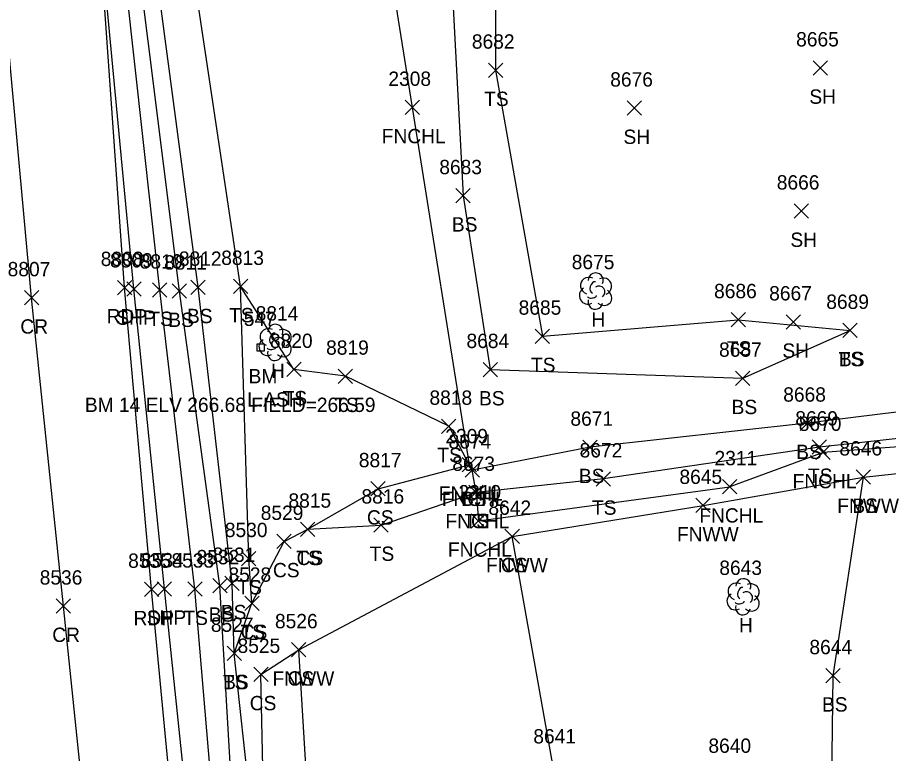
# Model space of a CAD drawing. Extents: x 1439173 to 1457902, y 641926 to 659889.
# Drawn here: x 1448353.5 to 1448474.9, y 645719.4 to 645822.1 of the extents above; entities that cross this region are included whole.
import ezdxf

# ---------------------------------------------------------------- set-up
doc = ezdxf.new("R2010")
doc.units = 0
for name, color, linetype in [('C_A', 7, 'Continuous'), ('C_C', 7, 'Continuous'), ('C_I', 7, 'Continuous'), ('CPBM', 7, 'Continuous'), ('L_A', 7, 'Continuous'), ('L_C', 7, 'Continuous'), ('L_I', 7, 'Continuous'), ('L_TIC', 7, 'Continuous'), ('LELB', 7, 'Continuous'), ('LFNC', 7, 'Continuous'), ('LTD', 7, 'Continuous'), ('P_A', 7, 'Continuous'), ('P_I', 7, 'Continuous'), ('P_TIC', 7, 'Continuous'), ('PET', 7, 'Continuous'), ('PRC', 7, 'Continuous'), ('PSP', 7, 'Continuous')]:
    doc.layers.add(name, color=color, linetype=linetype)

msp = doc.modelspace()

# ---------------------------------------------------------------- linework, layer by layer
at = {"layer": 'CPBM'}
for p, q in [((1448386.88, 645775.58), (1448386.88, 645776.58)), ((1448386.88, 645776.58), (1448387.88, 645776.58)), ((1448387.88, 645775.58), (1448386.88, 645775.58)), ((1448387.38, 645776.08), (1448387.38, 645776.08)), ((1448387.38, 645776.08), (1448387.38, 645776.08)), ((1448387.88, 645776.58), (1448387.88, 645775.58))]:
    msp.add_line(p, q, dxfattribs=at)
at = {"layer": 'L_TIC'}
for points in [[(1448419.13, 645813.76), (1448421.13, 645815.76)], [(1448421.13, 645813.76), (1448419.13, 645815.76)], [(1448464.39, 645814.07), (1448466.39, 645816.07)], [(1448466.39, 645814.07), (1448464.39, 645816.07)], [(1448407.52, 645808.57), (1448409.52, 645810.57)], [(1448409.52, 645808.57), (1448407.52, 645810.57)], [(1448438.47, 645808.47), (1448440.47, 645810.47)], [(1448440.47, 645808.47), (1448438.47, 645810.47)], [(1448414.59, 645796.25), (1448416.59, 645798.25)], [(1448416.59, 645796.25), (1448414.59, 645798.25)], [(1448461.74, 645794.11), (1448463.74, 645796.11)], [(1448463.74, 645794.11), (1448461.74, 645796.11)], [(1448377.66, 645783.47), (1448379.66, 645785.47)], [(1448379.66, 645783.47), (1448377.66, 645785.47)], [(1448383.57, 645783.59), (1448385.57, 645785.59)], [(1448385.57, 645783.59), (1448383.57, 645785.59)], [(1448372.3, 645783.08), (1448374.3, 645785.08)], [(1448374.3, 645783.08), (1448372.3, 645785.08)], [(1448375.05, 645782.94), (1448377.05, 645784.94)], [(1448377.05, 645782.94), (1448375.05, 645784.94)], [(1448452.96, 645778.95), (1448454.96, 645780.95)], [(1448454.96, 645778.95), (1448452.96, 645780.95)], [(1448460.62, 645778.64), (1448462.62, 645780.64)], [(1448462.62, 645778.64), (1448460.62, 645780.64)], [(1448468.55, 645777.46), (1448470.55, 645779.46)], [(1448470.55, 645777.46), (1448468.55, 645779.46)], [(1448468.55, 645777.46), (1448470.55, 645779.46)], [(1448470.55, 645777.46), (1448468.55, 645779.46)], [(1448425.65, 645776.65), (1448427.65, 645778.65)], [(1448427.65, 645776.65), (1448425.65, 645778.65)], [(1448391.02, 645772.01), (1448393.02, 645774.01)], [(1448393.02, 645772.01), (1448391.02, 645774.01)], [(1448418.38, 645772), (1448420.38, 645774)], [(1448420.38, 645772), (1448418.38, 645774)], [(1448398.2, 645771.07), (1448400.2, 645773.07)], [(1448400.2, 645771.07), (1448398.2, 645773.07)], [(1448453.59, 645770.78), (1448455.59, 645772.78)], [(1448455.59, 645770.78), (1448453.59, 645772.78)], [(1448412.6, 645764.08), (1448414.6, 645766.08)], [(1448414.6, 645764.08), (1448412.6, 645766.08)], [(1448462.59, 645764.52), (1448464.59, 645766.52)], [(1448464.59, 645764.52), (1448462.59, 645766.52)], [(1448432.3, 645761.16), (1448434.3, 645763.16)], [(1448434.3, 645761.16), (1448432.3, 645763.16)], [(1448464.27, 645761.19), (1448466.27, 645763.19)], [(1448466.27, 645761.19), (1448464.27, 645763.19)], [(1448464.78, 645760.44), (1448466.78, 645762.44)], [(1448466.78, 645760.44), (1448464.78, 645762.44)], [(1448415.46, 645758.71), (1448417.46, 645760.71)], [(1448417.46, 645758.71), (1448415.46, 645760.71)], [(1448415.88, 645757.97), (1448417.88, 645759.97)], [(1448417.88, 645757.97), (1448415.88, 645759.97)], [(1448415.88, 645757.97), (1448417.88, 645759.97)], [(1448417.88, 645757.97), (1448415.88, 645759.97)], [(1448434.15, 645756.74), (1448436.15, 645758.74)], [(1448436.15, 645756.74), (1448434.15, 645758.74)], [(1448470.42, 645757.01), (1448472.42, 645759.01)], [(1448472.42, 645757.01), (1448470.42, 645759.01)], [(1448470.42, 645757.01), (1448472.42, 645759.01)], [(1448472.42, 645757.01), (1448470.42, 645759.01)], [(1448402.75, 645755.37), (1448404.75, 645757.37)], [(1448404.75, 645755.37), (1448402.75, 645757.37)], [(1448451.78, 645755.65), (1448453.78, 645757.65)], [(1448453.78, 645755.65), (1448451.78, 645757.65)], [(1448416.4, 645754.87), (1448418.4, 645756.87)], [(1448418.4, 645754.87), (1448416.4, 645756.87)], [(1448416.4, 645754.87), (1448418.4, 645756.87)], [(1448418.4, 645754.87), (1448416.4, 645756.87)], [(1448448.06, 645753.04), (1448450.06, 645755.04)], [(1448450.06, 645753.04), (1448448.06, 645755.04)], [(1448416.73, 645750.89), (1448418.73, 645752.89)], [(1448418.73, 645750.89), (1448416.73, 645752.89)], [(1448392.94, 645749.73), (1448394.94, 645751.73)], [(1448394.94, 645749.73), (1448392.94, 645751.73)], [(1448392.94, 645749.73), (1448394.94, 645751.73)], [(1448394.94, 645749.73), (1448392.94, 645751.73)], [(1448403.17, 645750.31), (1448405.17, 645752.31)], [(1448405.17, 645750.31), (1448403.17, 645752.31)], [(1448421.44, 645748.73), (1448423.44, 645750.73)], [(1448423.44, 645748.73), (1448421.44, 645750.73)], [(1448421.44, 645748.73), (1448423.44, 645750.73)], [(1448423.44, 645748.73), (1448421.44, 645750.73)], [(1448389.64, 645748.02), (1448391.64, 645750.02)], [(1448391.64, 645748.02), (1448389.64, 645750.02)], [(1448384.72, 645745.63), (1448386.72, 645747.63)], [(1448386.72, 645745.63), (1448384.72, 645747.63)], [(1448382.38, 645742.17), (1448384.38, 645744.17)], [(1448384.38, 645742.17), (1448382.38, 645744.17)], [(1448377.2, 645741.37), (1448379.2, 645743.37)], [(1448379.2, 645741.37), (1448377.2, 645743.37)], [(1448380.69, 645741.83), (1448382.69, 645743.83)], [(1448382.69, 645741.83), (1448380.69, 645743.83)], [(1448385.15, 645739.4), (1448387.15, 645741.4)], [(1448387.15, 645739.4), (1448385.15, 645741.4)], [(1448385.15, 645739.4), (1448387.15, 645741.4)], [(1448387.15, 645739.4), (1448385.15, 645741.4)], [(1448382.69, 645732.41), (1448384.69, 645734.41)], [(1448384.69, 645732.41), (1448382.69, 645734.41)], [(1448382.69, 645732.41), (1448384.69, 645734.41)], [(1448384.69, 645732.41), (1448382.69, 645734.41)], [(1448391.68, 645732.91), (1448393.68, 645734.91)], [(1448393.68, 645732.91), (1448391.68, 645734.91)], [(1448391.68, 645732.91), (1448393.68, 645734.91)], [(1448393.68, 645732.91), (1448391.68, 645734.91)], [(1448386.41, 645729.47), (1448388.41, 645731.47)], [(1448388.41, 645729.47), (1448386.41, 645731.47)], [(1448466.19, 645729.29), (1448468.19, 645731.29)], [(1448468.19, 645729.29), (1448466.19, 645731.29)]]:
    msp.add_lwpolyline(points, dxfattribs=at)
at = {"layer": 'LELB'}
for points in [[(1448405.75, 645492.25), (1448401.29, 645509.86), (1448397.55, 645536.24), (1448395.04, 645565.43), (1448390.82, 645605.16), (1448386.96, 645640.23), (1448382.46, 645691.87), (1448378.2, 645742.37), (1448373.3, 645784.08), (1448367.48, 645837.06), (1448362.7, 645887.98), (1448357.78, 645935.33)], [(1448412.77, 645435.45), (1448410.01, 645448.83), (1448407.82, 645469.28), (1448405.75, 645492.25), (1448403.36, 645510.08), (1448399.67, 645536.29), (1448396.72, 645565.18), (1448393.06, 645605.09), (1448389.62, 645640.48), (1448384.68, 645691.72), (1448381.69, 645742.83), (1448376.05, 645783.94), (1448369.5, 645836.29), (1448364.45, 645888.25), (1448360.02, 645935.41)], [(1448403.36, 645510.08), (1448401.75, 645536.42), (1448399.06, 645565.21), (1448394.76, 645605.53), (1448391.92, 645640.7), (1448388.23, 645691.54), (1448383.69, 645733.41), (1448383.38, 645743.17), (1448378.66, 645784.47), (1448371.77, 645836.33), (1448366.28, 645888.78), (1448363.29, 645935.65)], [(1448383.69, 645733.41), (1448386.15, 645740.4), (1448385.72, 645746.63), (1448384.57, 645784.59), (1448376.84, 645836.17), (1448370.62, 645889.09), (1448366.48, 645935.68)], [(1448488.86, 645774.87), (1448485.16, 645804.97), (1448493.44, 645849.5), (1448484.69, 645866.76), (1448464.76, 645858.02), (1448427.96, 645849.9), (1448412.89, 645848.11), (1448415.59, 645797.25), (1448419.38, 645773), (1448454.59, 645771.78), (1448469.55, 645778.46)], [(1448493.44, 645849.5), (1448466.57, 645845.61), (1448437.38, 645832.99), (1448420.15, 645839.74), (1448420.13, 645814.76), (1448426.65, 645777.65), (1448453.96, 645779.95), (1448469.55, 645778.46)], [(1448392.02, 645773.01), (1448384.57, 645784.59)], [(1448413.6, 645765.08), (1448399.2, 645772.07), (1448392.02, 645773.01)], [(1448504.57, 645770.47), (1448489.22, 645768.67), (1448463.59, 645765.52), (1448433.3, 645762.16), (1448416.88, 645758.97)], [(1448505.1, 645766.43), (1448490.19, 645764.92), (1448465.27, 645762.19), (1448435.15, 645757.74), (1448417.4, 645755.87)], [(1448413.6, 645765.08), (1448416.46, 645759.71)], [(1448403.75, 645756.37), (1448416.46, 645759.71)], [(1448406.65, 645553.07), (1448413.88, 645573.37), (1448416.45, 645609.69), (1448416.69, 645643.68), (1448431.28, 645649.5), (1448456.82, 645674.35), (1448466.81, 645700.96), (1448467.19, 645730.29), (1448471.42, 645758.01)], [(1448386.15, 645740.4), (1448390.64, 645749.02), (1448393.94, 645750.73), (1448403.75, 645756.37)], [(1448404.17, 645751.31), (1448417.4, 645755.87)], [(1448393.94, 645750.73), (1448404.17, 645751.31)], [(1448440.92, 645562.38), (1448423.89, 645580.18), (1448428.08, 645611.99), (1448428.96, 645640.99), (1448431.28, 645649.5), (1448422.01, 645666.17), (1448428.13, 645717.84), (1448422.44, 645749.73)], [(1448388.23, 645691.54), (1448387.41, 645730.47), (1448392.68, 645733.91)]]:
    msp.add_lwpolyline(points, dxfattribs=at)
at = {"layer": 'LFNC'}
for points in [[(1448460.82, 645892.13), (1448433.93, 645874.65), (1448401.5, 645853.61), (1448408.52, 645809.57), (1448416.46, 645759.71)], [(1448504.76, 645764.38), (1448465.78, 645761.44)], [(1448408.71, 645537.14), (1448406.65, 645553.07), (1448406.84, 645570.83), (1448403.03, 645603.97), (1448399.71, 645645.27), (1448398.94, 645666), (1448395.14, 645693.25), (1448392.68, 645733.91), (1448422.44, 645749.73), (1448449.06, 645754.04), (1448471.42, 645758.01), (1448503.03, 645761.43), (1448501.38, 645735.65), (1448498.9, 645710.49)], [(1448465.78, 645761.44), (1448452.78, 645756.65)], [(1448416.88, 645758.97), (1448416.46, 645759.71)], [(1448417.4, 645755.87), (1448416.88, 645758.97)], [(1448417.73, 645751.89), (1448452.78, 645756.65)], [(1448417.4, 645755.87), (1448417.73, 645751.89)]]:
    msp.add_lwpolyline(points, dxfattribs=at)
at = {"layer": 'LTD'}
for p, q in [((1448434.05, 645784), (1448434.05, 645784)), ((1448434.05, 645784), (1448434.05, 645784)), ((1448389.37, 645776.83), (1448389.37, 645776.83)), ((1448389.37, 645776.83), (1448389.37, 645776.83)), ((1448454.62, 645741.35), (1448454.62, 645741.35)), ((1448454.62, 645741.35), (1448454.62, 645741.35))]:
    msp.add_line(p, q, dxfattribs=at)
for centre in [(1448434.09, 645785.43), (1448389.42, 645778.27), (1448454.67, 645742.78)]:
    msp.add_arc(centre, 1.05, 335.5272, 180.9563, dxfattribs=at)
for centre, major_axis, ratio, start_param, end_param in [((1448433.25, 645784.66), (1.21, -0.51), 0.895232, 1.570796, 4.712389), ((1448433.84, 645784.45), (-0.208, -0.792), 0.645439, 3.141593, 6.283185), ((1448435.09, 645784.58), (-1.14, -0.48), 0.949671, 1.570796, 4.712389), ((1448432.96, 645783.29), (0.58, -1.04), 0.959034, 3.141593, 6.283185), ((1448434.55, 645783.83), (-0.5, 0.667), 0.989748, 3.141593, 6.283185), ((1448435.05, 645783.16), (-1.09, 0.79), 0.841452, 1.570796, 4.712389), ((1448433.59, 645783.25), (-0.625, -0.083), 0.423636, 0, 3.141593), ((1448434.05, 645782.5), (0.26, 1.06), 0.942809, 1.570796, 4.712389), ((1448388.58, 645777.5), (1.21, -0.51), 0.895232, 1.570796, 4.712389), ((1448389.17, 645777.29), (-0.208, -0.792), 0.645439, 3.141593, 6.283185), ((1448390.42, 645777.41), (-1.14, -0.48), 0.949671, 1.570796, 4.712389), ((1448388.29, 645776.12), (0.58, -1.04), 0.959034, 3.141593, 6.283185), ((1448389.87, 645776.66), (-0.5, 0.667), 0.989748, 3.141593, 6.283185), ((1448390.37, 645776), (-1.09, 0.79), 0.841452, 1.570796, 4.712389), ((1448389.37, 645775.33), (0.26, 1.06), 0.942809, 1.570796, 4.712389), ((1448388.92, 645776.08), (-0.625, -0.083), 0.423636, 0, 3.141593), ((1448453.83, 645742.02), (1.21, -0.51), 0.895232, 1.570796, 4.712389), ((1448455.66, 645741.93), (-1.14, -0.48), 0.949671, 1.570796, 4.712389), ((1448453.54, 645740.64), (0.58, -1.04), 0.959034, 3.141593, 6.283185), ((1448454.41, 645741.81), (-0.208, -0.792), 0.645439, 3.141593, 6.283185), ((1448455.12, 645741.18), (-0.5, 0.667), 0.989748, 3.141593, 6.283185), ((1448454.16, 645740.6), (-0.625, -0.083), 0.423636, 0, 3.141593), ((1448455.62, 645740.52), (-1.09, 0.79), 0.841452, 1.570796, 4.712389), ((1448454.62, 645739.85), (0.26, 1.06), 0.942809, 1.570796, 4.712389)]:
    msp.add_ellipse(centre, major_axis=major_axis, ratio=ratio, start_param=start_param, end_param=end_param, dxfattribs=at)
at = {"layer": 'P_TIC'}
for points in [[(1448367.41, 645783.44), (1448369.41, 645785.44)], [(1448369.41, 645783.44), (1448367.41, 645785.44)], [(1448368.71, 645783.24), (1448370.71, 645785.24)], [(1448370.71, 645783.24), (1448368.71, 645785.24)], [(1448354.44, 645782.01), (1448356.44, 645784.01)], [(1448356.44, 645782.01), (1448354.44, 645784.01)], [(1448371.16, 645741.34), (1448373.16, 645743.34)], [(1448373.16, 645741.34), (1448371.16, 645743.34)], [(1448372.95, 645741.41), (1448374.95, 645743.41)], [(1448374.95, 645741.41), (1448372.95, 645743.41)], [(1448358.88, 645739), (1448360.88, 645741)], [(1448360.88, 645739), (1448358.88, 645741)]]:
    msp.add_lwpolyline(points, dxfattribs=at)
at = {"layer": 'PET'}
msp.add_lwpolyline([(1448443.5, 645192.53), (1448434.94, 645239.98), (1448429.99, 645267.41), (1448423.88, 645303.9), (1448416.59, 645352.86), (1448409.48, 645406.38), (1448407.14, 645423.82), (1448401.2, 645468.9), (1448395.52, 645519.79), (1448390.56, 645564.93), (1448385.73, 645605.17), (1448382.23, 645639.77), (1448376.98, 645691.5), (1448372.16, 645742.34), (1448368.41, 645784.44), (1448364.57, 645838.37), (1448359.79, 645887.7), (1448355.35, 645935.31)], dxfattribs=at)
at = {"layer": 'PRC'}
msp.add_lwpolyline([(1448432.04, 645191.01), (1448423.23, 645238.86), (1448418.18, 645266.5), (1448412.46, 645302.65), (1448405.18, 645350.69), (1448397.65, 645404.37), (1448395.39, 645422.98), (1448389.6, 645467.56), (1448383.62, 645518.18), (1448378.28, 645564.48), (1448373.77, 645604.55), (1448370.44, 645638.71), (1448365.01, 645690.62), (1448359.88, 645740), (1448355.44, 645783.01), (1448350.36, 645838.06), (1448345.39, 645887.63), (1448340.89, 645937.21)], dxfattribs=at)
at = {"layer": 'PSP'}
msp.add_lwpolyline([(1448445.7, 645193.09), (1448437.06, 645240), (1448432.32, 645267.62), (1448425.9, 645304.13), (1448419.15, 645353.02), (1448411.55, 645406.57), (1448409.06, 645424.19), (1448403.66, 645468.94), (1448397.6, 645519.68), (1448392.38, 645565.18), (1448387.87, 645605.22), (1448384.49, 645639.79), (1448379.25, 645691.61), (1448373.95, 645742.41), (1448369.71, 645784.24), (1448364.57, 645838.37)], dxfattribs=at)

# ---------------------------------------------------------------- texts
at = {"layer": 'C_A'}
msp.add_text('BM', height=2, dxfattribs=at).set_placement((1448385.69, 645771.08))
at = {"layer": 'C_C'}
msp.add_text('BM 14 ELV 266.68 FIELD=266.59', height=2, dxfattribs=at).set_placement((1448362.87, 645767.08))
at = {"layer": 'C_I'}
msp.add_text('547', height=2, dxfattribs=at).set_placement((1448385.02, 645779.08))
at = {"layer": 'L_A'}
for s, p in [('SH', (1448463.87, 645810.07)), ('TS', (1448418.53, 645809.76)), ('FNCHL', (1448404.26, 645804.57)), ('SH', (1448437.96, 645804.47)), ('BS', (1448414.03, 645792.25)), ('SH', (1448461.23, 645790.11)), ('TS', (1448371.71, 645779.08)), ('BS', (1448374.49, 645778.94)), ('BS', (1448377.1, 645779.47)), ('TS', (1448382.98, 645779.59)), ('H', (1448433.48, 645779)), ('TS', (1448452.37, 645774.95)), ('SH', (1448460.11, 645774.64)), ('TS', (1448425.06, 645772.65)), ('TS', (1448467.96, 645773.46)), ('BS', (1448467.99, 645773.46)), ('H', (1448388.81, 645771.83)), ('TS', (1448390.43, 645768.01)), ('BS', (1448417.82, 645768)), ('TS', (1448397.61, 645767.07)), ('BS', (1448453.03, 645766.78)), ('BS', (1448462.03, 645760.52)), ('TS', (1448412.01, 645760.08)), ('BS', (1448431.74, 645757.16)), ('TS', (1448463.68, 645757.19)), ('FNCHL', (1448461.53, 645756.44)), ('FNCHL', (1448412.21, 645754.71)), ('FNCHL', (1448412.63, 645753.97)), ('BS', (1448415.32, 645753.97)), ('FNWW', (1448467.76, 645753.01)), ('BS', (1448469.86, 645753.01)), ('TS', (1448433.56, 645752.74)), ('CS', (1448402.19, 645751.37)), ('FNCHL', (1448413.14, 645750.87)), ('TS', (1448415.8, 645750.87)), ('FNCHL', (1448448.53, 645751.65)), ('FNWW', (1448445.41, 645749.04)), ('FNCHL', (1448413.48, 645746.89)), ('TS', (1448392.35, 645745.73)), ('CS', (1448392.38, 645745.73)), ('TS', (1448402.58, 645746.31)), ('FNWW', (1448418.79, 645744.73)), ('CS', (1448420.88, 645744.73)), ('CS', (1448389.09, 645744.02)), ('TS', (1448384.13, 645741.63)), ('TS', (1448376.61, 645737.37)), ('BS', (1448380.13, 645737.83)), ('BS', (1448381.82, 645738.17)), ('H', (1448454.06, 645736.35)), ('TS', (1448384.56, 645735.4)), ('CS', (1448384.59, 645735.4)), ('FNWW', (1448389.03, 645728.91)), ('CS', (1448391.12, 645728.91)), ('TS', (1448382.1, 645728.41)), ('BS', (1448382.14, 645728.41)), ('CS', (1448385.85, 645725.47)), ('BS', (1448465.63, 645725.29))]:
    msp.add_text(s, height=2, dxfattribs=at).set_placement(p)
at = {"layer": 'L_C'}
msp.add_text('L.ASH', height=2, dxfattribs=at).set_placement((1448385.5, 645767.83))
at = {"layer": 'L_I'}
for s, p in [('8682', (1448416.82, 645817.76)), ('8665', (1448462.03, 645818.07)), ('2308', (1448405.18, 645812.57)), ('8676', (1448436.11, 645812.47)), ('8683', (1448412.28, 645800.25)), ('8666', (1448459.33, 645798.11)), ('8810', (1448370.52, 645787.08)), ('8811', (1448373.92, 645786.94)), ('8812', (1448375.97, 645787.47)), ('8813', (1448381.88, 645787.59)), ('8675', (1448430.74, 645787)), ('8686', (1448450.59, 645782.95)), ('8667', (1448458.27, 645782.64)), ('8689', (1448466.23, 645781.46)), ('8689', (1448466.23, 645781.46)), ('8814', (1448386.68, 645779.83)), ('8685', (1448423.34, 645780.65)), ('8820', (1448388.67, 645776.01)), ('8684', (1448416.07, 645776)), ('8819', (1448396.5, 645775.07)), ('8687', (1448451.28, 645774.78)), ('8818', (1448410.91, 645768.08)), ('8668', (1448460.23, 645768.52)), ('8671', (1448430.56, 645765.16)), ('8669', (1448461.91, 645765.19)), ('8670', (1448462.39, 645764.44)), ('2309', (1448413.12, 645762.71)), ('8674', (1448413.57, 645761.97)), ('8674', (1448413.57, 645761.97)), ('8672', (1448431.84, 645760.74)), ('8646', (1448468.06, 645761.01)), ('8646', (1448468.06, 645761.01)), ('8817', (1448401.06, 645759.37)), ('2311', (1448450.65, 645759.65)), ('8673', (1448414.09, 645758.87)), ('8673', (1448414.09, 645758.87)), ('8645', (1448445.76, 645757.04)), ('8816', (1448401.43, 645754.31)), ('2310', (1448414.95, 645754.89)), ('8815', (1448391.25, 645753.73)), ('8815', (1448391.25, 645753.73)), ('8529', (1448387.38, 645752.02)), ('8642', (1448419.13, 645752.73)), ('8642', (1448419.13, 645752.73)), ('8530', (1448382.38, 645749.63)), ('8532', (1448378.43, 645745.83)), ('8531', (1448380.68, 645746.17)), ('8533', (1448374.94, 645745.37)), ('8528', (1448382.89, 645743.4)), ('8528', (1448382.89, 645743.4)), ('8643', (1448451.32, 645744.35)), ('8527', (1448380.43, 645736.41)), ('8527', (1448380.43, 645736.41)), ('8526', (1448389.37, 645736.91)), ('8526', (1448389.37, 645736.91)), ('8525', (1448384.15, 645733.47)), ('8644', (1448463.88, 645733.29)), ('8641', (1448425.39, 645720.84)), ('8640', (1448449.8, 645719.53))]:
    msp.add_text(s, height=2, dxfattribs=at).set_placement(p)
at = {"layer": 'P_A'}
for s, p in [('RDP', (1448365.9, 645779.44)), ('SHP', (1448367.25, 645779.24)), ('CR', (1448353.87, 645778.01)), ('RDP', (1448369.65, 645737.34)), ('SHP', (1448371.49, 645737.41)), ('CR', (1448358.32, 645735))]:
    msp.add_text(s, height=2, dxfattribs=at).set_placement(p)
at = {"layer": 'P_I'}
for s, p in [('8808', (1448365.08, 645787.44)), ('8809', (1448366.37, 645787.24)), ('8807', (1448352.1, 645786.01)), ('8535', (1448368.9, 645745.34)), ('8534', (1448370.69, 645745.41)), ('8536', (1448356.57, 645743))]:
    msp.add_text(s, height=2, dxfattribs=at).set_placement(p)

doc.saveas('drawing.dxf')
